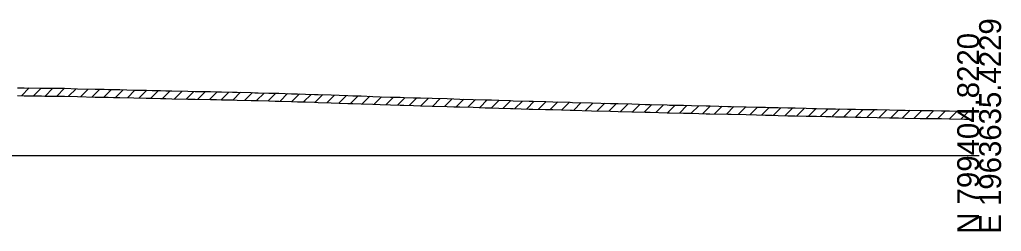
# Model space of a CAD drawing. Extents: x -26 to 1403, y -10 to 19587.
# Drawn here: x 277.5 to 402.8, y 18490.3 to 18517.3 of the extents above; entities that cross this region are included whole.
import ezdxf

# ---------------------------------------------------------------- set-up
doc = ezdxf.new("R2010")
doc.units = 0
for name, color, linetype in [('RD_GPK_XS_Cell', 7, 'Continuous'), ('RD_XS_ExGround', 7, 'Continuous'), ('RD_XS_ExPaveRet', 7, 'Continuous')]:
    doc.layers.add(name, color=color, linetype=linetype)

msp = doc.modelspace()

# ---------------------------------------------------------------- linework, layer by layer
at = {"layer": 'RD_GPK_XS_Cell'}
msp.add_line((200, 18500), (400, 18500), dxfattribs=at)
at = {"layer": 'RD_XS_ExGround'}
msp.add_lwpolyline([(277.19, 18508.62), (278.04, 18508.6), (280.25, 18508.57), (280.7, 18508.56), (282.8, 18508.56), (283.18, 18508.55), (284.87, 18508.49), (287.1, 18508.44), (288.25, 18508.42), (288.79, 18508.41), (289.45, 18508.39), (290.25, 18508.38), (292.04, 18508.33), (293.63, 18508.3), (294.37, 18508.28), (295.47, 18508.26), (296.13, 18508.24), (296.92, 18508.22), (298.94, 18508.17), (299.86, 18508.16), (301.85, 18508.13), (302.59, 18508.11), (303.25, 18508.09), (304.65, 18508.06), (305.26, 18508.05), (307.04, 18508), (307.5, 18507.99), (307.93, 18507.98), (309.28, 18507.94), (310.11, 18507.92), (310.55, 18507.91), (312.19, 18507.86), (312.96, 18507.84), (313.97, 18507.81), (315.12, 18507.77), (315.58, 18507.76), (317.25, 18507.7), (318.29, 18507.67), (319.36, 18507.63), (320, 18507.61), (321.06, 18507.57), (322.55, 18507.52), (323.52, 18507.48), (324.82, 18507.44), (326.04, 18507.41), (326.53, 18507.39), (327.78, 18507.35), (328.66, 18507.32), (330.15, 18507.28), (332.06, 18507.23), (332.93, 18507.2), (333.67, 18507.18), (335.38, 18507.14), (336.91, 18507.08), (337.71, 18507.06), (338.66, 18507.03), (340.15, 18506.98), (340.51, 18506.97), (342.53, 18506.91), (343.02, 18506.9), (344.6, 18506.85), (345.54, 18506.83), (347.76, 18506.77), (348.09, 18506.76), (350.48, 18506.69), (352.94, 18506.63), (353.91, 18506.6), (355.65, 18506.55), (357.34, 18506.5), (357.99, 18506.49), (360.14, 18506.43), (360.46, 18506.42), (362.26, 18506.38), (363.28, 18506.36), (365.12, 18506.31), (365.62, 18506.3), (367.91, 18506.25), (368.32, 18506.24), (370.25, 18506.19), (371.55, 18506.16), (372.73, 18506.13), (373.21, 18506.12), (373.56, 18506.11), (374.34, 18506.09), (375.55, 18506.06), (376.51, 18506.04), (377.9, 18506.01), (378.7, 18505.99), (379.23, 18505.98), (380.42, 18505.95), (381.04, 18505.94), (381.65, 18505.93), (383.17, 18505.9), (384.2, 18505.88), (384.91, 18505.86), (386.97, 18505.83), (388.56, 18505.8), (389.69, 18505.78), (390.57, 18505.76), (392.48, 18505.72), (394.03, 18505.7), (395.18, 18505.68), (396.22, 18505.66), (398.12, 18505.63), (398.52, 18505.62), (400, 18505.6)], dxfattribs=at)
at = {"layer": 'RD_XS_ExPaveRet'}
for p, q in [((277.72, 18507.61), (278.7, 18508.59)), ((279.22, 18507.59), (280.2, 18508.57)), ((280.72, 18507.56), (281.72, 18508.56)), ((282.22, 18507.56), (283.2, 18508.55)), ((283.72, 18507.53), (284.68, 18508.49)), ((285.22, 18507.48), (286.2, 18508.46)), ((286.72, 18507.45), (287.7, 18508.43)), ((288.22, 18507.42), (289.19, 18508.4)), ((289.72, 18507.39), (290.69, 18508.36)), ((291.22, 18507.35), (292.19, 18508.33)), ((292.72, 18507.32), (293.7, 18508.3)), ((294.22, 18507.28), (295.2, 18508.27)), ((295.72, 18507.25), (296.69, 18508.22)), ((297.22, 18507.21), (298.2, 18508.19)), ((298.72, 18507.18), (299.7, 18508.16)), ((300.22, 18507.15), (301.2, 18508.14)), ((301.72, 18507.13), (302.7, 18508.11)), ((277.19, 18507.62), (278.04, 18507.6)), ((278.04, 18507.6), (280.25, 18507.57)), ((280.25, 18507.57), (280.7, 18507.56)), ((280.7, 18507.56), (282.8, 18507.56)), ((282.8, 18507.56), (283.18, 18507.55)), ((283.18, 18507.55), (284.87, 18507.49)), ((284.87, 18507.49), (287.1, 18507.44)), ((287.1, 18507.44), (288.25, 18507.42)), ((288.25, 18507.42), (288.79, 18507.41)), ((288.79, 18507.41), (289.45, 18507.39)), ((289.45, 18507.39), (290.25, 18507.38)), ((290.25, 18507.38), (292.04, 18507.33)), ((292.04, 18507.33), (293.63, 18507.3)), ((293.63, 18507.3), (294.37, 18507.28)), ((294.37, 18507.28), (295.47, 18507.26)), ((295.47, 18507.26), (296.13, 18507.24)), ((296.13, 18507.24), (296.92, 18507.22)), ((296.92, 18507.22), (298.94, 18507.17)), ((298.94, 18507.17), (299.86, 18507.16)), ((299.86, 18507.16), (301.85, 18507.13)), ((301.85, 18507.13), (302.59, 18507.11)), ((302.59, 18507.11), (303.25, 18507.09)), ((303.22, 18507.1), (304.19, 18508.07)), ((303.25, 18507.09), (304.65, 18507.06)), ((304.65, 18507.06), (305.26, 18507.05)), ((304.72, 18507.06), (305.69, 18508.04)), ((305.26, 18507.05), (307.04, 18507)), ((306.22, 18507.02), (307.19, 18508)), ((307.04, 18507), (307.5, 18506.99)), ((307.5, 18506.99), (307.93, 18506.98)), ((307.72, 18506.98), (308.69, 18507.95)), ((307.93, 18506.98), (309.28, 18506.94)), ((309.22, 18506.94), (310.19, 18507.92)), ((309.28, 18506.94), (310.11, 18506.92)), ((310.11, 18506.92), (310.55, 18506.91)), ((310.55, 18506.91), (312.19, 18506.86)), ((310.72, 18506.9), (311.69, 18507.87)), ((312.19, 18506.86), (312.96, 18506.84)), ((312.22, 18506.86), (313.19, 18507.83)), ((313.72, 18506.82), (314.69, 18507.78)), ((315.22, 18506.77), (316.19, 18507.74)), ((316.72, 18506.72), (317.69, 18507.69)), ((318.22, 18506.67), (319.19, 18507.64)), ((319.72, 18506.62), (320.68, 18507.59)), ((321.22, 18506.57), (322.18, 18507.53)), ((322.72, 18506.51), (323.68, 18507.48)), ((324.22, 18506.46), (325.19, 18507.43)), ((325.72, 18506.42), (326.68, 18507.38)), ((327.22, 18506.37), (328.19, 18507.34)), ((328.72, 18506.32), (329.69, 18507.29)), ((330.22, 18506.28), (331.19, 18507.25)), ((331.72, 18506.24), (332.69, 18507.21)), ((333.22, 18506.2), (334.19, 18507.17)), ((334.72, 18506.15), (335.69, 18507.13)), ((336.22, 18506.11), (337.18, 18507.08)), ((337.72, 18506.06), (338.69, 18507.03)), ((339.22, 18506.01), (340.19, 18506.98)), ((340.72, 18505.96), (341.69, 18506.93)), ((342.22, 18505.92), (343.19, 18506.89)), ((343.72, 18505.88), (344.69, 18506.85)), ((312.96, 18506.84), (313.97, 18506.81)), ((313.97, 18506.81), (315.12, 18506.77)), ((315.12, 18506.77), (315.58, 18506.76)), ((315.58, 18506.76), (317.25, 18506.7)), ((317.25, 18506.7), (318.29, 18506.67)), ((318.29, 18506.67), (319.36, 18506.63)), ((319.36, 18506.63), (320, 18506.61)), ((320, 18506.61), (321.06, 18506.57)), ((321.06, 18506.57), (322.55, 18506.52)), ((322.55, 18506.52), (323.52, 18506.48)), ((323.52, 18506.48), (324.82, 18506.44)), ((324.82, 18506.44), (326.04, 18506.41)), ((326.04, 18506.41), (326.53, 18506.39)), ((326.53, 18506.39), (327.78, 18506.35)), ((327.78, 18506.35), (328.66, 18506.32)), ((328.66, 18506.32), (330.15, 18506.28)), ((330.15, 18506.28), (332.06, 18506.23)), ((332.06, 18506.23), (332.93, 18506.2)), ((332.93, 18506.2), (333.67, 18506.18)), ((333.67, 18506.18), (335.38, 18506.14)), ((335.38, 18506.14), (336.91, 18506.08)), ((336.91, 18506.08), (337.71, 18506.06)), ((337.71, 18506.06), (338.66, 18506.03)), ((338.66, 18506.03), (340.15, 18505.98)), ((340.15, 18505.98), (340.51, 18505.97)), ((340.51, 18505.97), (342.53, 18505.91)), ((342.53, 18505.91), (343.02, 18505.9)), ((343.02, 18505.9), (344.6, 18505.85)), ((344.6, 18505.85), (345.54, 18505.83)), ((345.22, 18505.84), (346.19, 18506.81)), ((345.54, 18505.83), (347.76, 18505.77)), ((346.72, 18505.8), (347.69, 18506.77)), ((347.76, 18505.77), (348.09, 18505.76)), ((348.09, 18505.76), (350.48, 18505.69)), ((348.22, 18505.76), (349.19, 18506.73)), ((349.72, 18505.71), (350.69, 18506.69)), ((350.48, 18505.69), (352.94, 18505.63)), ((351.22, 18505.67), (352.19, 18506.65)), ((352.72, 18505.63), (353.69, 18506.61)), ((352.94, 18505.63), (353.91, 18505.6)), ((353.91, 18505.6), (355.65, 18505.55)), ((354.22, 18505.59), (355.19, 18506.56)), ((355.72, 18505.55), (356.69, 18506.52)), ((357.22, 18505.51), (358.19, 18506.48)), ((358.72, 18505.47), (359.69, 18506.44)), ((360.22, 18505.43), (361.19, 18506.41)), ((361.72, 18505.39), (362.69, 18506.37)), ((363.22, 18505.36), (364.19, 18506.33)), ((364.72, 18505.32), (365.69, 18506.3)), ((366.22, 18505.29), (367.19, 18506.26)), ((367.72, 18505.25), (368.69, 18506.23)), ((369.22, 18505.22), (370.19, 18506.19)), ((370.72, 18505.18), (371.69, 18506.15)), ((372.22, 18505.14), (373.19, 18506.12)), ((373.72, 18505.11), (374.69, 18506.08)), ((375.22, 18505.07), (376.19, 18506.05)), ((376.72, 18505.03), (377.7, 18506.01)), ((378.22, 18505), (379.2, 18505.98)), ((379.72, 18504.97), (380.7, 18505.95)), ((381.22, 18504.94), (382.2, 18505.92)), ((382.72, 18504.91), (383.7, 18505.89)), ((384.22, 18504.88), (385.2, 18505.86)), ((385.72, 18504.85), (386.7, 18505.83)), ((387.22, 18504.82), (388.2, 18505.8)), ((388.72, 18504.79), (389.7, 18505.78)), ((390.22, 18504.77), (391.2, 18505.75)), ((391.72, 18504.74), (392.7, 18505.72)), ((393.22, 18504.71), (394.2, 18505.7)), ((394.72, 18504.69), (395.7, 18505.67)), ((396.22, 18504.66), (397.2, 18505.64)), ((397.72, 18504.64), (398.7, 18505.62)), ((399.11, 18505.61), (399.11, 18504.61)), ((355.65, 18505.55), (357.34, 18505.5)), ((357.34, 18505.5), (357.99, 18505.49)), ((357.99, 18505.49), (360.14, 18505.43)), ((360.14, 18505.43), (360.46, 18505.42)), ((360.46, 18505.42), (362.26, 18505.38)), ((362.26, 18505.38), (363.28, 18505.36)), ((363.28, 18505.36), (365.12, 18505.31)), ((365.12, 18505.31), (365.62, 18505.3)), ((365.62, 18505.3), (367.91, 18505.25)), ((367.91, 18505.25), (368.32, 18505.24)), ((368.32, 18505.24), (370.25, 18505.19)), ((370.25, 18505.19), (371.55, 18505.16)), ((371.55, 18505.16), (372.73, 18505.13)), ((372.73, 18505.13), (373.21, 18505.12)), ((373.21, 18505.12), (373.56, 18505.11)), ((373.56, 18505.11), (374.34, 18505.09)), ((374.34, 18505.09), (375.55, 18505.06)), ((375.55, 18505.06), (376.51, 18505.04)), ((376.51, 18505.04), (377.9, 18505.01)), ((377.9, 18505.01), (378.7, 18504.99)), ((378.7, 18504.99), (379.23, 18504.98)), ((379.23, 18504.98), (380.42, 18504.95)), ((380.42, 18504.95), (381.04, 18504.94)), ((381.04, 18504.94), (381.65, 18504.93)), ((381.65, 18504.93), (383.17, 18504.9)), ((383.17, 18504.9), (384.2, 18504.88)), ((384.2, 18504.88), (384.91, 18504.86)), ((384.91, 18504.86), (386.97, 18504.83)), ((386.97, 18504.83), (388.56, 18504.8)), ((388.56, 18504.8), (389.69, 18504.78)), ((389.69, 18504.78), (390.57, 18504.76)), ((390.57, 18504.76), (392.48, 18504.72)), ((392.48, 18504.72), (394.03, 18504.7)), ((394.03, 18504.7), (395.18, 18504.68)), ((395.18, 18504.68), (396.22, 18504.66)), ((396.22, 18504.66), (398.12, 18504.63)), ((398.12, 18504.63), (398.52, 18504.62)), ((398.52, 18504.62), (399.11, 18504.61))]:
    msp.add_line(p, q, dxfattribs=at)

# ---------------------------------------------------------------- texts
at = {"layer": 'RD_GPK_XS_Cell'}
for s, p in [('E 1963635.4229', (402.8, 18490)), ('N 799404.8220', (400, 18490))]:
    msp.add_text(s, height=2.8, rotation=90, dxfattribs=at).set_placement(p)

doc.saveas('drawing.dxf')
